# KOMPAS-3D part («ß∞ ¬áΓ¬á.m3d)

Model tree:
1. Эскиз:1
2. Операция выдавливания:1
     Расстояние 1 = 4
3. Эскиз:2
4. Операция выдавливания:2
     Расстояние 1 = 3.4
5. Эскиз:3
6. Операция выдавливания:3
     Расстояние 1 = 20
7. Условное изображение резьбы:1
     Длина резьбы = 4; Шаг резьбы = 1.25; Номинальный диаметр резьбы = 5
8. Условное изображение резьбы:2
     Длина резьбы = 8; Шаг резьбы = 1.25; Номинальный диаметр резьбы = 5
9. Скругление:1
     Радиус = 0.1

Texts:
  ось опорного катка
